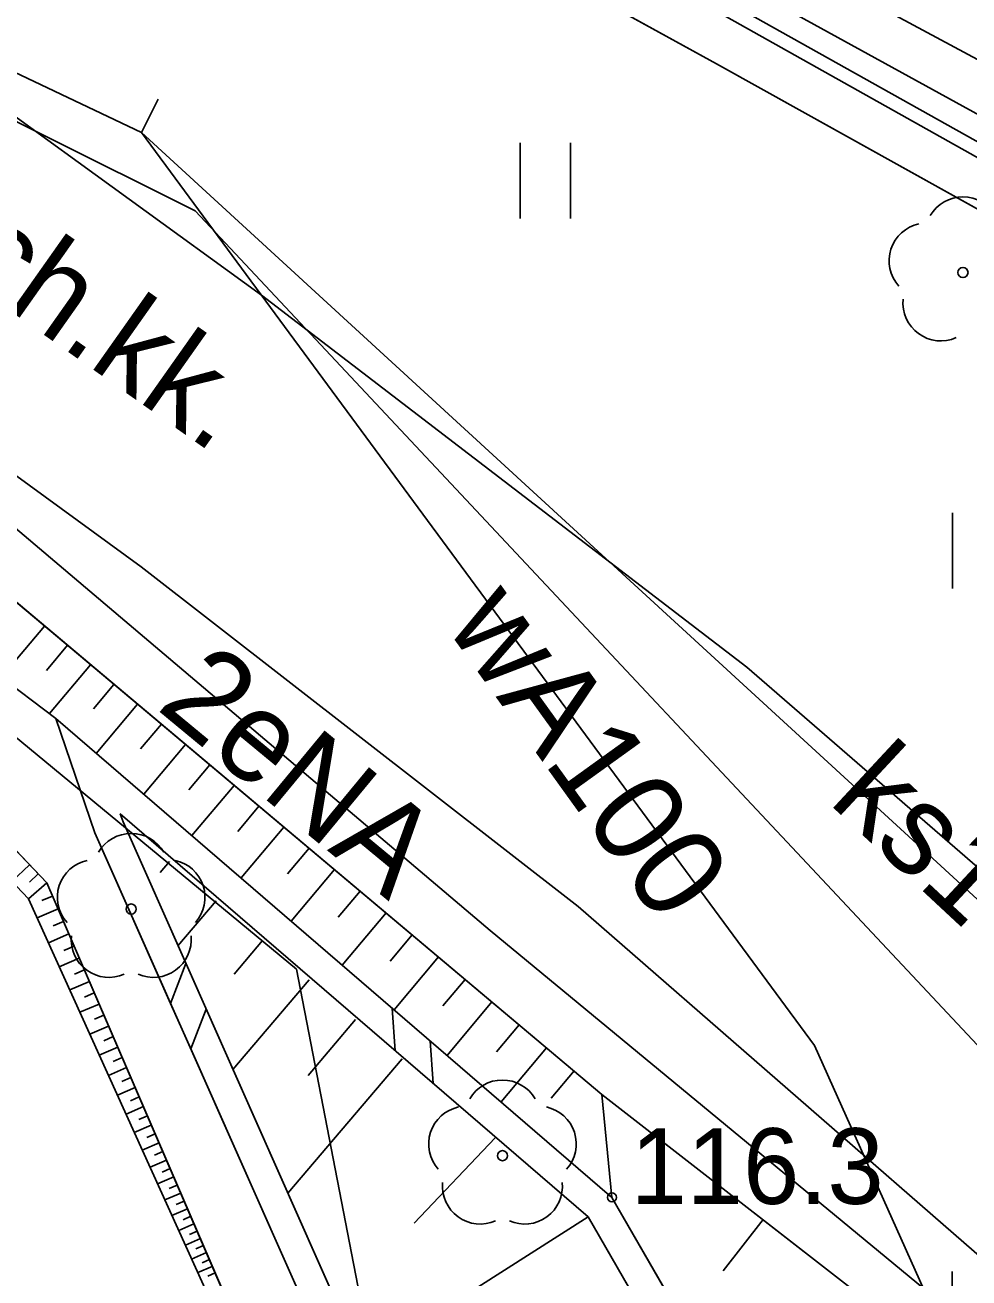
# Model space of a CAD drawing. Extents: x 6434771 to 6436222, y 5663454 to 5664782.
# Drawn here: x 6434959.2 to 6434968.56, y 5664024.19 to 5664036.61 of the extents above; entities that cross this region are included whole.
import ezdxf

# ---------------------------------------------------------------- set-up
doc = ezdxf.new("R2010")
doc.units = 0
for name, color, linetype in [('Warstwa 1', 7, 'Continuous'), ('Warstwa 10', 7, 'Continuous'), ('Warstwa 11', 7, 'Continuous'), ('Warstwa 12', 7, 'Continuous'), ('Warstwa 13', 7, 'Continuous'), ('Warstwa 2', 7, 'Continuous'), ('Warstwa 20', 7, 'Continuous'), ('Warstwa 21', 7, 'Continuous'), ('Warstwa 5', 7, 'Continuous'), ('Warstwa 51', 7, 'Continuous'), ('Warstwa 6', 7, 'Continuous'), ('Warstwa 7', 7, 'Continuous'), ('Warstwa 8', 7, 'Continuous'), ('Warstwa 9', 7, 'Continuous')]:
    doc.layers.add(name, color=color, linetype=linetype)

msp = doc.modelspace()

# ---------------------------------------------------------------- linework, layer by layer
at = {"layer": 'Warstwa 1'}
for p, q in [((6434951.952, 5664044.671), (6434980.58, 5664028.593)), ((6434951.952, 5664044.671), (6434980.58, 5664028.593)), ((6434955.627, 5664032.428), (6434961.887, 5664027.254)), ((6434961.887, 5664027.254), (6434963.44, 5664019.243))]:
    msp.add_line(p, q, dxfattribs=at)
at = {"layer": 'Warstwa 10'}
for p, q in [((6434958.066, 5664031.766), (6434964.917, 5664026.013)), ((6434957.589, 5664031.182), (6434959.502, 5664029.739)), ((6434959.389, 5664030.655), (6434958.962, 5664030.147)), ((6434959.617, 5664030.465), (6434959.408, 5664030.216)), ((6434959.846, 5664030.272), (6434959.439, 5664029.787)), ((6434960.078, 5664030.077), (6434959.875, 5664029.835)), ((6434960.312, 5664029.88), (6434959.903, 5664029.393)), ((6434959.502, 5664029.739), (6434965.015, 5664024.992)), ((6434960.548, 5664029.682), (6434960.342, 5664029.437)), ((6434960.787, 5664029.482), (6434960.373, 5664028.989)), ((6434961.028, 5664029.28), (6434960.82, 5664029.032)), ((6434961.27, 5664029.076), (6434960.851, 5664028.578)), ((6434961.516, 5664028.87), (6434961.305, 5664028.619)), ((6434960.141, 5664028.793), (6434960.168, 5664028.714)), ((6434960.141, 5664028.793), (6434964.781, 5664024.798)), ((6434960.168, 5664028.714), (6434960.168, 5664028.714)), ((6434960.168, 5664028.714), (6434962.539, 5664023.375)), ((6434961.763, 5664028.662), (6434961.339, 5664028.158)), ((6434962.013, 5664028.452), (6434961.8, 5664028.199)), ((6434960.629, 5664028.322), (6434960.535, 5664028.211)), ((6434962.264, 5664028.241), (6434961.835, 5664027.731)), ((6434962.519, 5664028.027), (6434962.302, 5664027.77)), ((6434961.09, 5664027.931), (6434960.713, 5664027.486)), ((6434962.776, 5664027.812), (6434962.341, 5664027.294)), ((6434961.552, 5664027.539), (6434961.269, 5664027.205)), ((6434963.034, 5664027.594), (6434962.816, 5664027.334)), ((6434963.297, 5664027.375), (6434962.856, 5664026.85)), ((6434962.013, 5664027.147), (6434961.258, 5664026.259)), ((6434963.56, 5664027.153), (6434963.339, 5664026.889)), ((6434963.826, 5664026.929), (6434963.381, 5664026.399)), ((6434962.474, 5664026.756), (6434962.002, 5664026.2)), ((6434964.096, 5664026.703), (6434963.871, 5664026.436)), ((6434964.367, 5664026.475), (6434963.916, 5664025.938)), ((6434962.935, 5664026.365), (6434961.803, 5664025.033)), ((6434964.641, 5664026.245), (6434964.414, 5664025.975)), ((6434965.015, 5664024.992), (6434964.917, 5664026.013)), ((6434964.917, 5664026.013), (6434965.015, 5664024.992)), ((6434964.917, 5664026.013), (6434972.903, 5664019.801)), ((6434963.857, 5664025.582), (6434963.054, 5664024.737)), ((6434965.015, 5664024.992), (6434968.336, 5664019.231)), ((6434964.781, 5664024.798), (6434962.539, 5664023.375)), ((6434964.781, 5664024.798), (6434968.082, 5664019.07)), ((6434966.515, 5664024.771), (6434966.12, 5664024.264))]:
    msp.add_line(p, q, dxfattribs=at)
msp.add_lwpolyline([(6434898.671, 5664074.419), (6434902.76, 5664072.365), (6434912.576, 5664067.627), (6434922.039, 5664062.843), (6434928.491, 5664059.745), (6434937.421, 5664055.317), (6434945.409, 5664050.998), (6434960.407, 5664042.783), (6434962.523, 5664038.882), (6434979.882, 5664029.167), (6434995.86, 5664020.139), (6435019.103, 5664006.754), (6435039.449, 5663995.035), (6435046.546, 5663989.977), (6435049.657, 5663987.84), (6435051.881, 5663986.317), (6435053.049, 5663985.633), (6435057.374, 5663981.038), (6435060.712, 5663977.517), (6435062.186, 5663975.788), (6435062.844, 5663975.005)], dxfattribs=at)
at = {"layer": 'Warstwa 11'}
msp.add_lwpolyline([(6434966.756, 5664003.6), (6434966.415, 5664007.644), (6434965.276, 5664011.028), (6434962.407, 5664016.883), (6434961.412, 5664023.136), (6434959.23, 5664027.952), (6434956.702, 5664030.613), (6434952.189, 5664033.718), (6434942.648, 5664038.634), (6434938.947, 5664040.259), (6434935.85, 5664038.056), (6434933.246, 5664036.108), (6434929.415, 5664035.234), (6434925.755, 5664033.559), (6434924.242, 5664028.377), (6434923.988, 5664023.91), (6434923.741, 5664023.373), (6434924.496, 5664011.353), (6434925.122, 5664008.575), (6434925.857, 5664004.846)], dxfattribs=at)
for centre in [(6434968.496, 5664034.16), (6434960.249, 5664027.85), (6434963.93, 5664025.405)]:
    msp.add_circle(centre, 0.05, dxfattribs=at)
for centre, start, end in [((6434968.496, 5664034.535), 30.1471, 149.8529), ((6434968.139, 5664034.276), 102.1471, 221.8529), ((6434968.276, 5664033.857), 174.1471, 293.8529), ((6434960.249, 5664028.225), 30.1471, 149.8529), ((6434959.892, 5664027.966), 102.1471, 221.8529), ((6434960.606, 5664027.966), 318.1471, 77.8529), ((6434960.029, 5664027.547), 174.1471, 293.8529), ((6434960.469, 5664027.547), 246.1471, 5.8529), ((6434963.93, 5664025.78), 30.1471, 149.8529), ((6434963.573, 5664025.521), 102.1471, 221.8529), ((6434964.287, 5664025.521), 318.1471, 77.8529), ((6434963.71, 5664025.102), 174.1471, 293.8529), ((6434964.15, 5664025.102), 246.1471, 5.8529)]:
    msp.add_arc(centre, 0.375, start, end, dxfattribs=at)
at = {"layer": 'Warstwa 12'}
for points in [[(6434879.158, 5664078.856), (6434884.466, 5664077.041), (6434884.943, 5664076.892), (6434885.361, 5664076.61), (6434904.643, 5664068.316), (6434925.269, 5664058.705), (6434945.05, 5664048.685), (6434974.567, 5664032.476), (6434974.989, 5664032.261), (6434975.127, 5664032.48), (6434976.891, 5664035.328), (6434977.019, 5664035.547), (6434977.471, 5664035.311), (6435021.423, 5664010.318), (6435021.865, 5664010.097), (6435021.856, 5664009.772), (6435020.661, 5664007.687), (6435020.508, 5664007.434), (6435020.935, 5664007.143), (6435043.134, 5663993.734), (6435056.442, 5663986.832), (6435065.286, 5663979.645), (6435065.567, 5663979.291)], [(6434928.096, 5664058.264), (6434929.076, 5664057.604), (6434939.486, 5664051.98), (6434948.125, 5664047.34), (6434952.325, 5664045.068), (6434966.421, 5664037.465), (6434988.007, 5664025.883), (6434989.76, 5664024.876), (6434992.028, 5664023.706), (6434998.449, 5664019.821), (6435020.142, 5664006.907), (6435038.86, 5663995.783), (6435047.805, 5663990.452), (6435048.936, 5663989.958)], [(6434924.809, 5664048.81), (6434930.739, 5664046.248), (6434938.087, 5664045.169), (6434947.585, 5664041.614), (6434960.352, 5664035.549), (6434967.024, 5664026.498), (6434969.107, 5664021.852), (6434976.011, 5664009.728), (6434981.103, 5663994.095), (6434983.23, 5663981.509), (6434983.428, 5663980.457), (6434983.606, 5663978.684), (6434986.797, 5663964.645), (6434990.011, 5663952.113)], [(6434916.87, 5664040.657), (6434919.588, 5664040.514), (6434924.045, 5664039.35), (6434927.322, 5664041.55), (6434931.207, 5664042.783), (6434934.74, 5664042.98), (6434942.258, 5664041.148), (6434950.666, 5664036.716), (6434956.042, 5664033.861), (6434958.491, 5664032.141), (6434963.807, 5664027.637), (6434974.145, 5664019.101)], [(6434960.352, 5664035.549), (6434960.516, 5664035.877)]]:
    msp.add_lwpolyline(points, dxfattribs=at)
at = {"layer": 'Warstwa 13'}
msp.add_circle((6434965.015, 5664024.992), 0.045, dxfattribs=at)
at = {"layer": 'Warstwa 2'}
for points in [[(6434921.661, 5664034.898), (6434922.705, 5664038.576), (6434924.532, 5664039.094), (6434926.338, 5664040.422), (6434928.301, 5664041.518), (6434930.459, 5664042.152), (6434933.603, 5664042.424), (6434935.842, 5664042.316), (6434938.067, 5664041.859), (6434940.24, 5664041.293), (6434942.361, 5664040.517), (6434946.478, 5664038.627), (6434952.38, 5664035.426), (6434958.066, 5664031.766), (6434964.917, 5664026.013)], [(6434978.489, 5664029.309), (6434966.051, 5664036.23), (6434958.65, 5664040.3), (6434957.922, 5664040.508)], [(6434938.635, 5663986.4), (6434948.754, 5663984.547), (6434955.481, 5663984.236), (6434959.951, 5663984.231), (6434964.407, 5663984.717), (6434968.731, 5663985.805), (6434972.687, 5663987.947), (6434975.856, 5663991.119), (6434979.564, 5663996.714), (6434981.354, 5664000.823), (6434983.144, 5664004.931), (6434980.889, 5664013.589), (6434972.903, 5664019.801), (6434964.917, 5664026.013)]]:
    msp.add_lwpolyline(points, dxfattribs=at)
at = {"layer": 'Warstwa 20'}
for p, q in [((6434958.066, 5664031.766), (6434964.917, 5664026.013)), ((6434960.141, 5664028.793), (6434964.781, 5664024.798)), ((6434964.917, 5664026.013), (6434972.903, 5664019.801)), ((6434964.781, 5664024.798), (6434968.082, 5664019.07))]:
    msp.add_line(p, q, dxfattribs=at)
msp.add_lwpolyline([(6434960.104, 5663994.36), (6434961.978, 5663995.497), (6434964.425, 5663998.568), (6434966.182, 5664001.617), (6434966.937, 5664003.658), (6434966.575, 5664007.652), (6434965.418, 5664011.176), (6434962.588, 5664017.021), (6434961.543, 5664023.174), (6434959.412, 5664028.11), (6434956.785, 5664030.862), (6434952.251, 5664033.867), (6434949.683, 5664035.19), (6434942.69, 5664038.793)], dxfattribs=at)
at = {"layer": 'Warstwa 21'}
for p, q in [((6434957.589, 5664031.182), (6434959.502, 5664029.739)), ((6434959.502, 5664029.739), (6434965.015, 5664024.992)), ((6434960.141, 5664028.793), (6434960.168, 5664028.714)), ((6434960.168, 5664028.714), (6434962.539, 5664023.375)), ((6434965.015, 5664024.992), (6434968.336, 5664019.231))]:
    msp.add_line(p, q, dxfattribs=at)
msp.add_lwpolyline([(6434959.587, 5663994.626), (6434961.932, 5663995.818), (6434964.397, 5663998.698), (6434966.084, 5664001.768), (6434966.756, 5664003.6), (6434966.415, 5664007.644), (6434965.276, 5664011.028), (6434962.407, 5664016.883), (6434961.412, 5664023.136), (6434959.23, 5664027.952), (6434956.702, 5664030.613), (6434952.189, 5664033.718), (6434942.648, 5664038.634)], dxfattribs=at)
at = {"layer": 'Warstwa 5'}
for p, q in [((6434958.65, 5664040.3), (6434966.051, 5664036.23)), ((6434957.519, 5664036.849), (6434961.542, 5664033.936)), ((6434966.051, 5664036.23), (6434978.489, 5664029.309)), ((6434964.104, 5664034.695), (6434964.104, 5664035.445)), ((6434964.604, 5664034.695), (6434964.604, 5664035.445)), ((6434955.889, 5664034.478), (6434960.349, 5664031.242)), ((6434961.542, 5664033.936), (6434966.352, 5664030.248)), ((6434958.066, 5664031.766), (6434964.917, 5664026.013)), ((6434968.393, 5664031.029), (6434968.393, 5664031.779)), ((6434960.349, 5664031.242), (6434964.681, 5664027.874)), ((6434957.589, 5664031.182), (6434959.502, 5664029.739)), ((6434956.785, 5664030.862), (6434959.412, 5664028.11)), ((6434966.352, 5664030.248), (6434976.339, 5664021.585)), ((6434959.502, 5664029.739), (6434959.888, 5664028.604)), ((6434959.888, 5664028.604), (6434960.638, 5664026.915)), ((6434959.412, 5664028.11), (6434961.543, 5664023.174)), ((6434964.681, 5664027.874), (6434968.888, 5664024.21)), ((6434960.638, 5664026.915), (6434960.839, 5664026.463)), ((6434960.839, 5664026.463), (6434962.264, 5664023.255)), ((6434964.917, 5664026.013), (6434972.903, 5664019.801)), ((6434968.388, 5664023.506), (6434968.388, 5664024.256))]:
    msp.add_line(p, q, dxfattribs=at)
at = {"layer": 'Warstwa 51'}
for p, q in [((6434960.639, 5664026.915), (6434960.791, 5664027.31)), ((6434962.867, 5664026.445), (6434962.837, 5664026.867)), ((6434960.839, 5664026.463), (6434960.992, 5664026.859)), ((6434963.243, 5664026.121), (6434963.212, 5664026.545))]:
    msp.add_line(p, q, dxfattribs=at)
for points in [[(6434964.229, 5663991.48), (6434967.04, 5663994.016), (6434970.273, 5663998.357), (6434972.461, 5664006.421), (6434972.681, 5664012.988), (6434968.336, 5664019.231), (6434965.015, 5664024.992), (6434959.502, 5664029.739), (6434959.888, 5664028.604), (6434962.264, 5664023.255), (6434963.353, 5664020.692), (6434965.402, 5664015.677), (6434968.698, 5664003.766), (6434969.642, 5664002.375), (6434968.965, 5664001.013), (6434967.057, 5664000.376), (6434965.915, 5663997.75), (6434964.819, 5663994.763), (6434963.407, 5663993.75)], [(6434964.028, 5663991.702), (6434966.818, 5663994.219), (6434969.999, 5663998.49), (6434972.162, 5664006.465), (6434972.377, 5664012.899), (6434968.082, 5664019.07), (6434964.781, 5664024.798), (6434960.141, 5664028.793), (6434960.168, 5664028.714), (6434962.539, 5664023.375), (6434963.63, 5664020.808), (6434965.687, 5664015.774), (6434968.974, 5664003.894), (6434969.988, 5664002.399), (6434969.178, 5664000.768), (6434967.279, 5664000.133), (6434966.194, 5663997.638), (6434965.069, 5663994.573), (6434963.582, 5663993.506)]]:
    msp.add_lwpolyline(points, dxfattribs=at)
at = {"layer": 'Warstwa 6'}
msp.add_lwpolyline([(6435199.169, 5663878.85), (6435069.683, 5663952.11), (6435070.435, 5663958.091), (6435069.483, 5663961.233), (6435068.325, 5663963.837), (6435062.043, 5663974.514), (6435058.095, 5663979.622), (6435055.831, 5663981.839), (6435050.759, 5663985.791), (6435026.957, 5664002.35), (6434999.334, 5664017.996), (6434991.09, 5664022.666), (6434980.58, 5664028.593), (6434951.952, 5664044.671), (6434942.859, 5664049.431), (6434933.864, 5664054.041), (6434925.132, 5664058.117), (6434918.181, 5664061.441), (6434909.328, 5664065.359), (6434902.911, 5664068.147), (6434896.533, 5664070.874)], dxfattribs=at)
msp.add_lwpolyline([(6435026.957, 5664002.35), (6435050.759, 5663985.791), (6435055.831, 5663981.839), (6435058.095, 5663979.622), (6435062.043, 5663974.514), (6435068.325, 5663963.837), (6435069.483, 5663961.233), (6435070.435, 5663958.091), (6435069.683, 5663952.11), (6435120.043, 5663983.972), (6435070.884, 5664005.038), (6435011.285, 5664038.642), (6434957.736, 5664068.872), (6434942.859, 5664049.431), (6434951.952, 5664044.671), (6434980.58, 5664028.593), (6434991.09, 5664022.666), (6434999.334, 5664017.996)], close=True, dxfattribs=at)
at = {"layer": 'Warstwa 7'}
for points in [[(6434932.526, 5664039.935), (6434932.833, 5664040.333), (6434937.258, 5664046.07), (6434937.622, 5664046.315), (6434938.316, 5664046.028), (6434960.883, 5664034.772), (6434973.659, 5664021.147), (6434974.001, 5664020.658), (6434974.526, 5664016.746), (6434981.103, 5663994.095), (6434983.279, 5663980.96)], [(6434960.516, 5664035.877), (6434960.352, 5664035.549), (6434973.215, 5664023.743), (6434973.286, 5664023.312), (6434995.263, 5664004.719), (6434995.671, 5664004.448), (6435025.261, 5663984.54), (6435077.854, 5663969.472)]]:
    msp.add_lwpolyline(points, dxfattribs=at)
at = {"layer": 'Warstwa 8'}
for p, q in [((6434958.65, 5664040.3), (6434966.051, 5664036.23)), ((6434966.051, 5664036.23), (6434978.489, 5664029.309))]:
    msp.add_line(p, q, dxfattribs=at)
at = {"layer": 'Warstwa 9'}
for p, q in [((6434957.519, 5664036.849), (6434961.542, 5664033.936)), ((6434955.889, 5664034.478), (6434960.349, 5664031.242)), ((6434961.542, 5664033.936), (6434966.352, 5664030.248)), ((6434960.349, 5664031.242), (6434964.681, 5664027.874)), ((6434966.352, 5664030.248), (6434976.339, 5664021.585)), ((6434959.24, 5664028.289), (6434959.067, 5664028.124)), ((6434959.412, 5664028.11), (6434959.23, 5664027.952)), ((6434959.326, 5664028.2), (6434959.239, 5664028.117)), ((6434959.469, 5664027.978), (6434959.364, 5664027.934)), ((6434964.681, 5664027.874), (6434968.888, 5664024.21)), ((6434959.524, 5664027.852), (6434959.316, 5664027.762)), ((6434959.578, 5664027.727), (6434959.475, 5664027.682)), ((6434959.631, 5664027.603), (6434959.428, 5664027.516)), ((6434959.734, 5664027.364), (6434959.535, 5664027.278)), ((6434959.683, 5664027.483), (6434959.582, 5664027.44)), ((6434959.785, 5664027.246), (6434959.686, 5664027.205)), ((6434959.834, 5664027.132), (6434959.64, 5664027.048)), ((6434959.883, 5664027.019), (6434959.787, 5664026.977)), ((6434959.931, 5664026.908), (6434959.741, 5664026.826)), ((6434959.978, 5664026.798), (6434959.884, 5664026.757)), ((6434960.025, 5664026.69), (6434959.838, 5664026.61)), ((6434960.071, 5664026.585), (6434959.978, 5664026.545)), ((6434960.116, 5664026.481), (6434959.933, 5664026.403)), ((6434960.159, 5664026.379), (6434960.069, 5664026.34)), ((6434960.203, 5664026.278), (6434960.023, 5664026.2)), ((6434960.246, 5664026.18), (6434960.157, 5664026.141)), ((6434960.288, 5664026.082), (6434960.112, 5664026.006)), ((6434960.37, 5664025.892), (6434960.198, 5664025.818)), ((6434960.329, 5664025.987), (6434960.242, 5664025.949)), ((6434960.409, 5664025.8), (6434960.324, 5664025.763)), ((6434960.448, 5664025.709), (6434960.279, 5664025.636)), ((6434960.525, 5664025.531), (6434960.359, 5664025.459)), ((6434960.487, 5664025.62), (6434960.404, 5664025.584)), ((6434960.562, 5664025.445), (6434960.481, 5664025.41)), ((6434960.599, 5664025.36), (6434960.436, 5664025.29)), ((6434960.635, 5664025.277), (6434960.555, 5664025.242)), ((6434960.671, 5664025.195), (6434960.511, 5664025.126)), ((6434960.74, 5664025.034), (6434960.583, 5664024.966)), ((6434960.706, 5664025.113), (6434960.627, 5664025.079)), ((6434960.807, 5664024.879), (6434960.652, 5664024.812)), ((6434960.773, 5664024.955), (6434960.696, 5664024.922)), ((6434960.839, 5664024.804), (6434960.763, 5664024.77)), ((6434960.871, 5664024.729), (6434960.72, 5664024.664)), ((6434960.904, 5664024.656), (6434960.828, 5664024.624)), ((6434960.935, 5664024.583), (6434960.786, 5664024.519)), ((6434960.965, 5664024.513), (6434960.89, 5664024.481)), ((6434960.995, 5664024.444), (6434960.848, 5664024.38)), ((6434961.053, 5664024.308), (6434960.91, 5664024.246)), ((6434961.024, 5664024.375), (6434960.952, 5664024.344)), ((6434961.082, 5664024.242), (6434961.01, 5664024.21))]:
    msp.add_line(p, q, dxfattribs=at)
msp.add_lwpolyline([(6434966.937, 5664003.658), (6434966.575, 5664007.652), (6434965.418, 5664011.176), (6434962.588, 5664017.021), (6434961.543, 5664023.174), (6434959.412, 5664028.11), (6434956.785, 5664030.862), (6434952.251, 5664033.867), (6434949.683, 5664035.19), (6434942.69, 5664038.793), (6434942.648, 5664038.634), (6434952.189, 5664033.718), (6434956.702, 5664030.613), (6434959.23, 5664027.952), (6434961.412, 5664023.136), (6434962.407, 5664016.883), (6434965.276, 5664011.028), (6434966.415, 5664007.644), (6434966.756, 5664003.6)], dxfattribs=at)

# ---------------------------------------------------------------- texts
at = {"layer": 'Warstwa 13'}
for s, rotation, p in [('wA100', 305.7647, (6434963.352, 5664030.662)), ('2eNA', 320.4152, (6434960.485, 5664029.842))]:
    msp.add_text(s, height=0.9, rotation=rotation, dxfattribs=at).set_placement(p)
msp.add_text('116.3', height=0.75, dxfattribs=at).set_placement((6434965.2, 5664024.927))
at = {"layer": 'Warstwa 7'}
msp.add_text('ks150', height=0.9, rotation=317.0577, dxfattribs=at).set_placement((6434967.15, 5664028.909))
at = {"layer": 'Warstwa 9'}
msp.add_text('ch.kk.', height=0.9, rotation=324.7869, dxfattribs=at).set_placement((6434958.496, 5664034.168))

doc.saveas('drawing.dxf')
